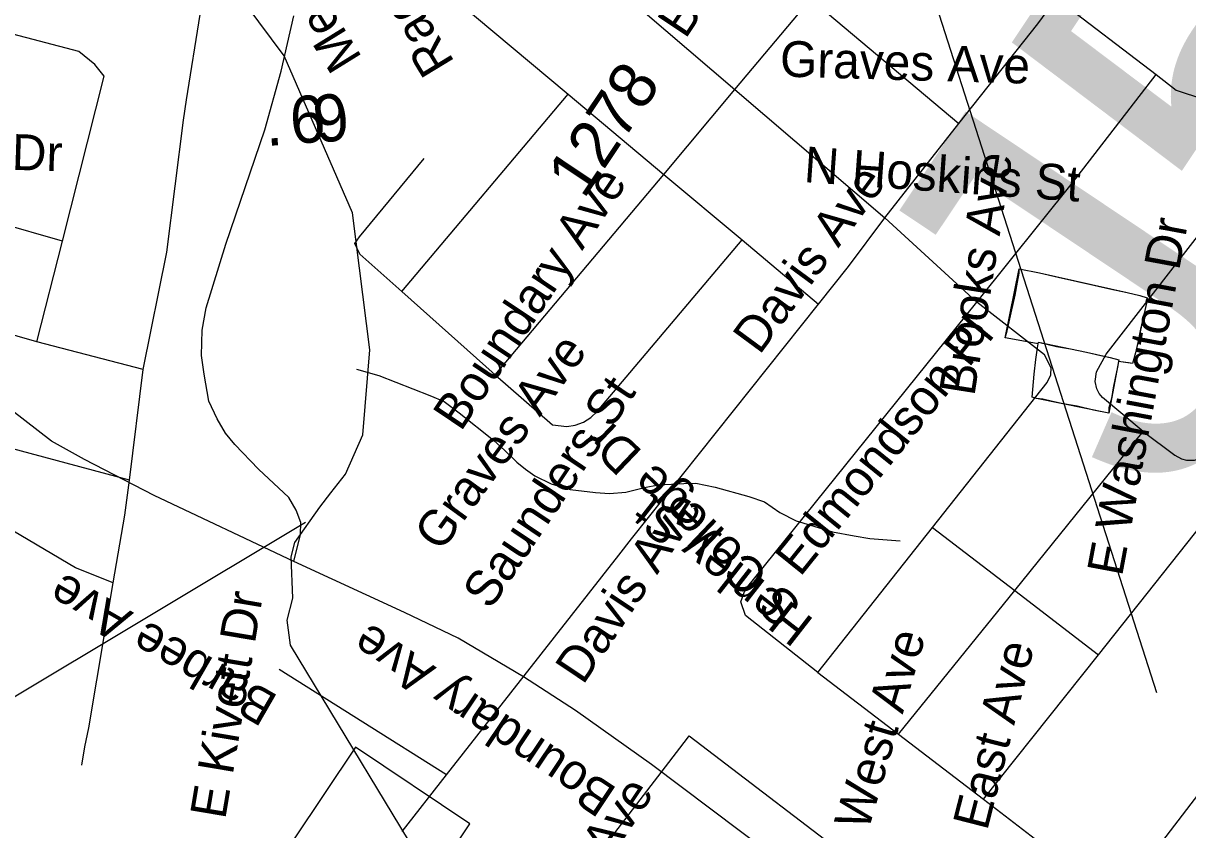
# Model space of a CAD drawing. Extents: x 1716282 to 1717158, y 799307 to 801078.
# Drawn here: x 1716763.01 to 1716807.84, y 800775.82 to 800806.86 of the extents above; entities that cross this region are included whole.
import ezdxf

# ---------------------------------------------------------------- set-up
doc = ezdxf.new("R2010")
doc.units = 0
for name, color, linetype in [('Exist Hydrographic Misc Water Feature', 7, 'Continuous'), ('Exist Road Non-System Structure Non-Sys Other Number Label', 7, 'Continuous'), ('Exist Road Non-System Type 51', 7, 'Continuous'), ('Exist Road Non-System Type 51 Label', 7, 'Continuous'), ('Exist Road Secondary Mileage Tenths English Label', 7, 'Continuous'), ('Exist Road Secondary Structure Culvert Number Label', 7, 'Continuous'), ('Exist Road Secondary Structure NCDOT Private Pedestrian Number Label', 7, 'Continuous'), ('Exist Road Secondary Structure Standard Bridge Number Label', 7, 'Continuous'), ('Exist Road Secondary Type 51 Attributed', 7, 'Continuous'), ('Exist Road Secondary Type 51 Label', 7, 'Continuous'), ('Exist Road Secondary Type 51 Number Label', 7, 'Continuous')]:
    doc.layers.add(name, color=color, linetype=linetype)

msp = doc.modelspace()

# ---------------------------------------------------------------- linework, layer by layer
at = {"layer": 'Exist Hydrographic Misc Water Feature'}
for points in [[(1716779.752, 800768.606), (1716779.969, 800768.981), (1716779.06, 800773.412), (1716773.302, 800782.926), (1716773.169, 800783.886), (1716773.397, 800784.735), (1716773.329, 800786.33), (1716773.47, 800786.879), (1716774.435, 800788.237), (1716774.859, 800788.785), (1716775.418, 800789.507), (1716776.092, 800791.022), (1716776.356, 800794.292), (1716775.692, 800799.57), (1716773.061, 800805.606), (1716767.28, 800813.366), (1716762.4, 800818.012), (1716761.079, 800818.592)], [(1716802.088, 800794.518), (1716801.31, 800794.665), (1716800.813, 800794.759), (1716800.888, 800795.022), (1716801.049, 800795.721), (1716801.193, 800796.396), (1716801.287, 800796.893), (1716801.347, 800797.239), (1716801.356, 800797.406), (1716802.135, 800797.261), (1716802.858, 800797.085), (1716803.597, 800796.93), (1716804.23, 800796.78), (1716804.84, 800796.644), (1716805.515, 800796.499), (1716805.995, 800796.38), (1716806.285, 800796.29), (1716806.257, 800796.096), (1716806.157, 800795.64), (1716806.029, 800795.093), (1716805.919, 800794.571), (1716805.826, 800794.177), (1716805.717, 800793.762), (1716805.564, 800793.794), (1716805.179, 800793.848)], [(1716802.088, 800794.518), (1716801.31, 800794.665), (1716800.813, 800794.759), (1716801.356, 800797.406), (1716802.135, 800797.261), (1716805.515, 800796.499), (1716805.995, 800796.38), (1716806.285, 800796.29), (1716806.257, 800796.096), (1716806.157, 800795.64), (1716805.919, 800794.571), (1716805.826, 800794.177), (1716805.717, 800793.762), (1716805.179, 800793.848)], [(1716805.179, 800793.848), (1716805.136, 800793.631), (1716805.051, 800793.198), (1716804.975, 800792.829), (1716804.906, 800792.419), (1716804.804, 800792.065), (1716804.803, 800791.856), (1716804.217, 800791.977), (1716803.583, 800792.129), (1716803.044, 800792.214), (1716802.586, 800792.315), (1716802.258, 800792.4), (1716802.024, 800792.419), (1716801.848, 800792.469), (1716801.932, 800793.363), (1716801.993, 800793.916), (1716802.055, 800794.366), (1716802.088, 800794.518)], [(1716805.179, 800793.848), (1716804.803, 800791.856), (1716802.024, 800792.419), (1716801.848, 800792.469), (1716801.932, 800793.363), (1716801.993, 800793.916), (1716802.055, 800794.366), (1716802.088, 800794.518)], [(1716802.088, 800794.518), (1716802.097, 800794.583), (1716802.795, 800794.422), (1716803.334, 800794.335), (1716803.943, 800794.199), (1716804.49, 800794.073), (1716804.858, 800793.996), (1716805.188, 800793.912), (1716805.179, 800793.848)], [(1716802.088, 800794.518), (1716802.097, 800794.583), (1716803.334, 800794.335), (1716803.943, 800794.199), (1716804.858, 800793.996), (1716805.188, 800793.912), (1716805.179, 800793.848)], [(1716775.848, 800793.544), (1716776.706, 800793.308), (1716778.669, 800792.531), (1716779.213, 800792.299), (1716779.796, 800791.866), (1716781.12, 800790.821), (1716781.549, 800790.422), (1716782.011, 800789.966), (1716782.354, 800789.697), (1716782.713, 800789.45), (1716783.337, 800789.131), (1716784.068, 800788.914), (1716785.048, 800788.805), (1716785.578, 800788.76), (1716786.215, 800788.817), (1716786.933, 800788.993), (1716787.456, 800789.091), (1716787.972, 800789.127), (1716788.446, 800789.153), (1716788.905, 800789.156), (1716789.644, 800789.003), (1716790.943, 800788.643), (1716791.545, 800788.442), (1716792.143, 800788.033), (1716792.767, 800787.712), (1716794.162, 800787.286), (1716795.005, 800787.132), (1716795.608, 800787.036), (1716796.773, 800786.943)]]:
    msp.add_lwpolyline(points, dxfattribs=at)
at = {"layer": 'Exist Road Non-System Type 51'}
for p, q in [((1716802.788, 800807.834), (1716806.624, 800804.887)), ((1716790.405, 800804.316), (1716793.33, 800807.804)), ((1716793.33, 800807.804), (1716799.024, 800803.003)), ((1716787.667, 800801.047), (1716790.405, 800804.316)), ((1716790.405, 800804.316), (1716796.183, 800799.369)), ((1716769.178, 800803.132), (1716769.303, 800803.915)), ((1716777.588, 800796.533), (1716783.993, 800804.131)), ((1716783.993, 800804.131), (1716787.667, 800801.047)), ((1716796.183, 800799.369), (1716799.024, 800803.003)), ((1716781.185, 800793.325), (1716787.667, 800801.047)), ((1716787.667, 800801.047), (1716790.683, 800798.521)), ((1716764.524, 800798.477), (1716760.486, 800799.622)), ((1716796.183, 800799.369), (1716799.716, 800796.128)), ((1716763.54, 800794.597), (1716764.524, 800798.477)), ((1716790.683, 800798.521), (1716793.624, 800796.053)), ((1716777.588, 800796.533), (1716781.185, 800793.325)), ((1716763.54, 800794.597), (1716759.439, 800795.779)), ((1716786.432, 800787.017), (1716793.624, 800796.053)), ((1716767.626, 800793.532), (1716763.54, 800794.597)), ((1716767.103, 800789.276), (1716767.626, 800793.532)), ((1716801.18, 800785.028), (1716806.13, 800791.146)), ((1716793.603, 800781.875), (1716798.021, 800787.459)), ((1716798.021, 800787.459), (1716801.18, 800785.028)), ((1716785.936, 800786.385), (1716786.432, 800787.017)), ((1716779.307, 800777.93), (1716785.936, 800786.385)), ((1716796.712, 800779.502), (1716801.18, 800785.028)), ((1716801.18, 800785.028), (1716804.4, 800782.553)), ((1716799.983, 800776.992), (1716804.4, 800782.553)), ((1716779.307, 800777.93), (1716772.865, 800781.984)), ((1716793.603, 800781.875), (1716796.712, 800779.502)), ((1716796.712, 800779.502), (1716799.983, 800776.992)), ((1716777.595, 800775.749), (1716779.307, 800777.93)), ((1716799.983, 800776.992), (1716802.863, 800774.789))]:
    msp.add_line(p, q, dxfattribs=at)
for points in [[(1716769.303, 800803.915), (1716769.829, 800807.203), (1716769.97, 800808.57), (1716771.825, 800817.843), (1716772.142, 800820.217), (1716772.306, 800821.92), (1716772.447, 800822.815)], [(1716779.582, 800813.388), (1716780.752, 800812.576), (1716790.405, 800804.316)], [(1716778.314, 800808.886), (1716780.383, 800807.155), (1716783.993, 800804.131)], [(1716799.024, 800803.003), (1716802.066, 800806.843), (1716802.788, 800807.834)], [(1716764.524, 800798.477), (1716766.128, 800804.821), (1716765.775, 800805.273), (1716765.153, 800805.772), (1716762.366, 800806.514)], [(1716799.716, 800796.128), (1716803.405, 800800.716), (1716806.624, 800804.887)], [(1716806.624, 800804.887), (1716807.396, 800804.292), (1716808.454, 800803.937), (1716810.056, 800803.647), (1716811.591, 800803)], [(1716767.626, 800793.532), (1716768.547, 800798.05), (1716769.178, 800803.132)], [(1716806.13, 800791.146), (1716804.566, 800792.461), (1716804.438, 800792.612), (1716804.345, 800792.788), (1716804.276, 800793.076), (1716804.327, 800793.445), (1716804.698, 800794.124), (1716811.591, 800803)], [(1716777.588, 800796.533), (1716775.969, 800797.972), (1716775.776, 800798.381), (1716775.959, 800798.648), (1716778.45, 800801.653)], [(1716793.624, 800796.053), (1716794.786, 800797.504), (1716796.183, 800799.369)], [(1716806.13, 800791.146), (1716807.343, 800790.242), (1716807.606, 800790.093), (1716807.8, 800790.046), (1716808.097, 800790.047), (1716808.379, 800790.147), (1716808.549, 800790.264), (1716809.027, 800790.827), (1716809.594, 800791.497), (1716814.55, 800797.964), (1716815.752, 800799.67)], [(1716781.185, 800793.325), (1716783.382, 800791.409), (1716783.936, 800791.34), (1716784.264, 800791.391), (1716784.583, 800791.506), (1716784.86, 800791.687), (1716785.104, 800791.923), (1716790.683, 800798.521)], [(1716793.603, 800781.875), (1716790.822, 800784.065), (1716790.631, 800784.588), (1716790.801, 800785.052), (1716799.716, 800796.128)], [(1716798.021, 800787.459), (1716802.433, 800793.031), (1716802.574, 800793.336), (1716802.58, 800793.607), (1716802.33, 800794.103), (1716799.716, 800796.128)], [(1716767.103, 800789.276), (1716760.493, 800791.052), (1716759.73, 800791.445), (1716758.062, 800792.745)], [(1716766.48, 800785.32), (1716765.027, 800785.902), (1716756.529, 800790.918)], [(1716766.48, 800785.32), (1716766.919, 800787.933), (1716767.103, 800789.276)], [(1716804.4, 800782.553), (1716808.742, 800788.019), (1716809.105, 800788.247), (1716809.4, 800788.305), (1716809.701, 800788.27), (1716809.892, 800788.192), (1716811.841, 800786.567)], [(1716765.266, 800778.302), (1716765.382, 800779.013), (1716765.534, 800779.739), (1716766.48, 800785.32)], [(1716785.62, 800775.478), (1716788.583, 800779.351), (1716788.648, 800779.436), (1716795.545, 800774.174)], [(1716802.863, 800774.789), (1716804.884, 800773.225), (1716805.066, 800773.14), (1716805.167, 800773.147), (1716808.732, 800777.803), (1716808.954, 800778.025)]]:
    msp.add_lwpolyline(points, dxfattribs=at)
at = {"layer": 'Exist Road Secondary Structure Culvert Number Label'}
msp.add_line((1716773.875, 800787.651), (1716761.964, 800780.512), dxfattribs=at)
at = {"layer": 'Exist Road Secondary Structure NCDOT Private Pedestrian Number Label'}
msp.add_lwpolyline([(1716776.622, 800770.701), (1716780.204, 800776.053), (1716775.802, 800778.999), (1716772.22, 800773.647)], dxfattribs=at)
at = {"layer": 'Exist Road Secondary Structure Standard Bridge Number Label'}
msp.add_line((1716806.647, 800781.09), (1716794.275, 800819.713), dxfattribs=at)
at = {"layer": 'Exist Road Secondary Type 51 Attributed'}
for points in [[(1716773.432, 800786.148), (1716773.689, 800787.187), (1716773.702, 800787.652), (1716773.521, 800788.116), (1716773.235, 800788.606), (1716772.072, 800789.7), (1716771.164, 800790.65), (1716770.805, 800791.083), (1716770.474, 800791.638), (1716770.16, 800792.322), (1716769.972, 800793.351), (1716769.88, 800794.079), (1716769.898, 800795.05), (1716770.053, 800795.911), (1716770.814, 800798.358), (1716772.318, 800802.756), (1716772.941, 800805.023), (1716773.43, 800807.144)], [(1716773.432, 800786.148), (1716768.058, 800788.684), (1716765.372, 800790.07), (1716764.095, 800790.784), (1716758.322, 800795.241)], [(1716809.029, 800761.998), (1716802.935, 800766.551), (1716795.791, 800771.947), (1716791.762, 800774.889), (1716787.196, 800778.327), (1716784.268, 800780.414), (1716782.265, 800781.702), (1716779.752, 800783.191), (1716777.695, 800784.181), (1716773.432, 800786.148)]]:
    msp.add_lwpolyline(points, dxfattribs=at)

# ---------------------------------------------------------------- texts
at = {"layer": 'Exist Road Non-System Structure Non-Sys Other Number Label'}
msp.add_text('J572', height=15.223, rotation=56.2051, dxfattribs=at).set_placement((1716807.118, 800787.797))
at = {"layer": 'Exist Road Non-System Type 51 Label'}
for s, rotation, p in [('Meadowbrook Blvd', 121.7735, (1716776.079, 800805.536)), ('Boundary Ave', 56.2051, (1716788.499, 800806.226)), ('Radford St', 121.3037, (1716779.64, 800805.358)), ('Graves Ave', 358.3413, (1716792.132, 800804.815)), ('N College Dr', 358.2234, (1716753.963, 800801.491)), ('N Hoskins St', 355.9357, (1716793.04, 800800.751)), ('Brooks Ave', 81.0125, (1716799.624, 800792.482)), ('Boundary Ave', 56.2051, (1716779.858, 800791.113)), ('Davis Ave', 53.6781, (1716791.356, 800794.066)), ('E Washington Dr', 79.4262, (1716805.309, 800785.539)), ('Edmondson Pl', 51.1385, (1716792.919, 800785.523)), ('Graves Ave', 53.8833, (1716779.092, 800786.472)), ('Saunders St', 56.2051, (1716780.994, 800784.247)), ('Davis Ave', 56.2051, (1716784.563, 800781.361)), ('Henley St', 142.0021, (1716793.502, 800783.883)), ('Barbee Ave', 150.0723, (1716772.876, 800780.951)), ('Boundary Ave', 146.2051, (1716785.921, 800777.39)), ('West Ave', 73.5685, (1716795.534, 800775.732)), ('East Ave', 75.6555, (1716800.117, 800775.75)), ('Crawford Ave', 56.2051, (1716781.124, 800767.97))]:
    msp.add_text(s, height=1.3775, rotation=rotation, dxfattribs=at).set_placement(p)
at = {"layer": 'Exist Road Secondary Mileage Tenths English Label'}
for s, rotation, p in [('6', 4.5395, (1716773.351, 800802.212)), ('9', 8.5473, (1716774.327, 800802.23)), ('.', 4.5395, (1716772.372, 800802.134))]:
    msp.add_text(s, height=1.812, rotation=rotation, dxfattribs=at).set_placement(p)
at = {"layer": 'Exist Road Secondary Type 51 Label'}
for s, rotation, p in [('S College Dr', 136.3308, (1716793.045, 800784.49)), ('E Kivett Dr', 80.4392, (1716770.786, 800776.19))]:
    msp.add_text(s, height=1.3775, rotation=rotation, dxfattribs=at).set_placement(p)
at = {"layer": 'Exist Road Secondary Type 51 Number Label'}
msp.add_text('1278', height=1.8125, rotation=56.2051, dxfattribs=at).set_placement((1716784.593, 800800.062))

doc.saveas('drawing.dxf')
